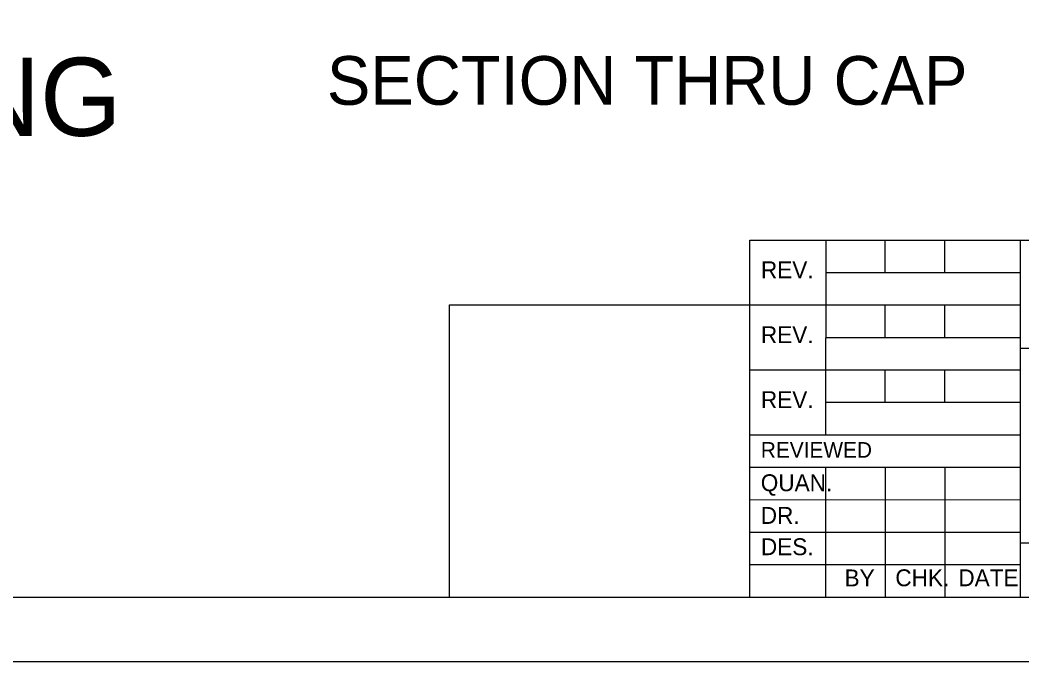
# Model space of a CAD drawing. Extents: x 437 to 537, y 571 to 720.
# Drawn here: x 498.74 to 519.95, y 654.41 to 668 of the extents above; entities that cross this region are included whole.
import ezdxf

# ---------------------------------------------------------------- set-up
doc = ezdxf.new("R2010")
doc.units = 0
for name, color, linetype in [('BR_BORDER LINES', 7, 'Continuous'), ('BR_REBAR', 7, 'Continuous'), ('BR_TEXT', 7, 'Continuous'), ('RD_SHT_IplotShp', 7, 'Continuous')]:
    doc.layers.add(name, color=color, linetype=linetype)

msp = doc.modelspace()

# ---------------------------------------------------------------- linework, layer by layer
at = {"layer": 'BR_BORDER LINES'}
for p, q in [((514.189, 655.781), (514.189, 663.344)), ((514.189, 663.344), (534.815, 663.343)), ((515.794, 663.344), (515.793, 659.219)), ((517.054, 662.656), (517.054, 663.344)), ((518.314, 662.656), (518.314, 663.344)), ((519.918, 655.781), (519.919, 663.344)), ((515.793, 662.656), (519.919, 662.656)), ((507.83, 661.969), (514.189, 661.969)), ((507.83, 655.781), (507.83, 661.969)), ((514.189, 661.969), (519.919, 661.969)), ((517.054, 661.281), (517.054, 661.969)), ((518.314, 661.281), (518.314, 661.969)), ((515.793, 661.281), (519.919, 661.281)), ((519.919, 661.052), (534.815, 661.051)), ((519.919, 661.052), (519.919, 661.052)), ((514.189, 660.594), (519.919, 660.594)), ((517.054, 659.906), (517.054, 660.594)), ((518.314, 659.906), (518.314, 660.594)), ((515.793, 659.906), (519.918, 659.906)), ((514.189, 659.219), (519.918, 659.219)), ((514.189, 658.531), (519.918, 658.531)), ((515.793, 658.531), (515.793, 655.781)), ((517.054, 658.531), (517.054, 655.781)), ((518.314, 658.531), (518.314, 655.781)), ((514.189, 657.844), (519.918, 657.843)), ((514.189, 657.156), (519.918, 657.156)), ((519.918, 656.927), (534.815, 656.926)), ((514.189, 656.469), (519.918, 656.468)), ((442.23, 655.783), (534.814, 655.78)), ((442.231, 655.78), (534.814, 655.78))]:
    msp.add_line(p, q, dxfattribs=at)
at = {"layer": 'RD_SHT_IplotShp'}
msp.add_lwpolyline([(437.19, 714.906), (536.19, 714.906), (536.19, 654.406), (437.19, 654.406)], close=True, dxfattribs=at)

# ---------------------------------------------------------------- texts
at = {"layer": 'BR_REBAR'}
msp.add_text('REVISE PILE SPACING', height=1.6543, dxfattribs=at).set_placement((476.787, 665.55))
at = {"layer": 'BR_TEXT'}
msp.add_text('SECTION THRU CAP', height=1.03125, dxfattribs=at).set_placement((505.234, 666.208))
for s, height, p in [('REV.', 0.3575, (514.422, 662.534)), ('REV.', 0.3575, (514.422, 661.159)), ('REV.', 0.3575, (514.422, 659.784)), ('REVIEWED', 0.33, (514.42, 658.733)), ('QUAN.', 0.3575, (514.419, 658.023)), ('DR.', 0.3575, (514.419, 657.331)), ('DES.', 0.3575, (514.422, 656.668)), ('BY', 0.3575, (516.193, 656.007)), ('CHK.', 0.3575, (517.268, 656.01)), ('DATE', 0.3575, (518.602, 656.01))]:
    msp.add_text(s, height=height, rotation=359.9982, dxfattribs=at).set_placement(p)

doc.saveas('drawing.dxf')
